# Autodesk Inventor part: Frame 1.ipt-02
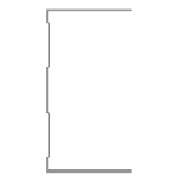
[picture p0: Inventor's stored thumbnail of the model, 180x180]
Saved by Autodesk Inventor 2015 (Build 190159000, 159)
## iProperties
IsCustomPart: 1
Created: 2015-04
Part Number: Frame 1.ipt-02
Material: Aluminum 6061
Description: Kévin Novo
Document SubType Name: Modeling
Standard: Kevin
Designer: suporte
Standards Organization: Kevin
Language: en-US
Size Designation: (Unnamed 2)
Categories: <MemberInstance><Categories><Category DisplayName="Structural Shapes" InternalName="089c4875-fa83-4c05-b084-43b9cc11f5ed" Mnemonic="GRDR"><CategoryParameter Dis
Density: 2.7 g/cm^3
Appearance: Aluminum - Flat
_CCFamilyMember: 2
_CCFamilyDisplayName: Kévin - Kévin Novo
_FrameMemberDoc: Frame Member File
_Version: 15.0.0
_GetPNFromCC: 1
G_W: 50,000 mm
G_H: 75,000 mm
G_L: 2100,000 mm
+E9F3D4D5-689B-44D8-B816-2A434F71FA07+CUTDETAIL1: Cut
+A000C5E7-CEB3-42E1-8513-AA5754572851+CUTDETAIL2: Notch
+31D064AA-8673-42EA-8666-D6E0756AEEA4+CUTDETAIL3: Cut
Author: suporte
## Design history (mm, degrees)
node "Start Plane"
node "End Plane"
sketch "Sketch"
  geometry: L1 (24.7, 37.5)-(24.7, 36.9); L2 (24.7, 36.9)-(-24.7, 36.9); L3 (-24.7, -36.9)-(24.7, -36.9); L4 (24.7, -36.9)-(24.7, -37.5); L5 (24.7, -37.5)-(-25.3, -37.5); L6 (-25.3, 37.5)-(24.7, 37.5); L7 (-24.7, 36.9)-(-24.7, 31.9); L8 (-24.7, 31.9)-(-23.3, 30.5); L9 (-23.3, 30.5)-(-23.3, 10.934); L10 (-23.3, 10.934)-(-24.7, 9.534); L11 (-24.7, 9.534)-(-24.7, -9.534); L12 (-24.7, -9.534)-(-23.3, -10.934); L13 (-23.3, -10.934)-(-23.3, -30.5); L14 (-23.3, -30.5)-(-24.7, -31.9); L15 (-24.7, -31.9)-(-24.7, -36.9); L16 (-25.3, -37.5)-(-25.3, -31.651); L17 (-25.3, -31.651)-(-23.9, -30.251); L18 (-23.9, -30.251)-(-23.9, -11.183); L19 (-23.9, -11.183)-(-25.3, -9.783); L20 (-25.3, -9.783)-(-25.3, 9.783); L21 (-25.3, 9.783)-(-23.9, 11.183); L22 (-23.9, 11.183)-(-23.9, 30.251); L23 (-23.9, 30.251)-(-25.3, 31.651); L24 (-25.3, 31.651)-(-25.3, 37.5); L25 (-25.3, 0)-(30.37, 0); 3 further points
  constraints: 50 end point, 10 point on line, 9 parallel, 5 perpendicular, 4 equal length, 3 midpoint, 3 vertical, 2 vertical alignment, 1 collinear, 1 horizontal, 1 horizontal alignment
  dimensions: "d3" = 0.6 distance of L1.start L1.end (= d6); "d5" = 75 distance between parallel lines of L5 L6; "d6" = 0.6 distance between parallel lines of L24 L7 (= d8); "d7" = 0.6 distance between parallel lines of L8 L23 (= d8); "d8" = 0.6 distance between parallel lines of L22 L9 (= d12); "Espessura" = 0.6 distance between parallel lines of L17 L14; "d10" = 0.6 distance between parallel lines of L13 L18 (= Espessura); "d11" = 0.6 distance between parallel lines of L12 L19 (= Espessura); "d12" = 0.6 distance between parallel lines of L21 L10 (= d11); "d13" = 5 distance of L2.end L7.end; "d15" = 135 deg angle of L9 L8; "d16" = 2 distance between parallel lines of L24 L9; "d17" = 50 distance of L6.start L1.start
extrude "Body" join sketch "Sketch" stored distance "d24" = 0.13; taper "d25" = 0 deg
node "Driven Length"
  sketch "Sketch10"
    geometry: L1 (0, 0)-(10, 0) reference
    constraints: 2 end point, 1 horizontal
  workplane "Work Plane7"
  sketch "Sketch11"
    geometry: L1 (-2, 0)-(12, 0) reference; L2 (-2, 2100)-(12, 2100) reference
    dimensions: "d27" = 2100 distance between parallel lines of L1 L2 (derived)
workplane "Work Plane8"
split "Split1"
workplane "Work Plane9"
workplane "Work Plane10"
workplane "Work Plane11"
sketch "Sketch12"
  geometry: L1 (24.7, 37.5)-(24.7, 36.9); L2 (24.7, 36.9)-(-24.7, 36.9); L3 (-24.7, 36.9)-(-24.7, 31.9); L4 (-24.7, 31.9)-(-23.3, 30.5); L5 (-23.3, 30.5)-(-23.3, 10.934); L6 (-23.3, 10.934)-(-24.7, 9.534); L7 (-24.7, 9.534)-(-24.7, -9.534); L8 (-24.7, -9.534)-(-23.3, -10.934); L9 (-23.3, -10.934)-(-23.3, -30.5); L10 (-23.3, -30.5)-(-24.7, -31.9); L11 (-24.7, -31.9)-(-24.7, -36.9); L12 (-24.7, -36.9)-(24.7, -36.9); L13 (24.7, -36.9)-(24.7, -37.5); L14 (24.7, -37.5)-(-25.3, -37.5); L15 (-25.3, -37.5)-(-25.3, -31.651); L16 (-25.3, -31.651)-(-23.9, -30.251); L17 (-23.9, -30.251)-(-23.9, -11.183); L18 (-23.9, -11.183)-(-25.3, -9.783); L19 (-25.3, -9.783)-(-25.3, 9.783); L20 (-25.3, 9.783)-(-23.9, 11.183); L21 (-23.9, 11.183)-(-23.9, 30.251); L22 (-23.9, 30.251)-(-25.3, 31.651); L23 (-25.3, 31.651)-(-25.3, 37.5); L24 (-25.3, 37.5)-(24.7, 37.5)
  constraints: 48 end point, 10 point on line
extrude "Extrusion3" cut sketch "Sketch12" stored distance "d36" = 0.13; taper "d37" = 0 deg
workplane "Work Plane12"
split "Split2"
body "Solid1"
other parameters: "G_OFFSET_START" = 0 [user parameter; used in 1 equation term], "G_OFFSET_END" = 0 [user parameter; used in 1 equation term], "d22" = 0 (computed from G_OFFSET_START), "G_L" = 2100 (= d27) [user parameter], "d34" = 90 deg
